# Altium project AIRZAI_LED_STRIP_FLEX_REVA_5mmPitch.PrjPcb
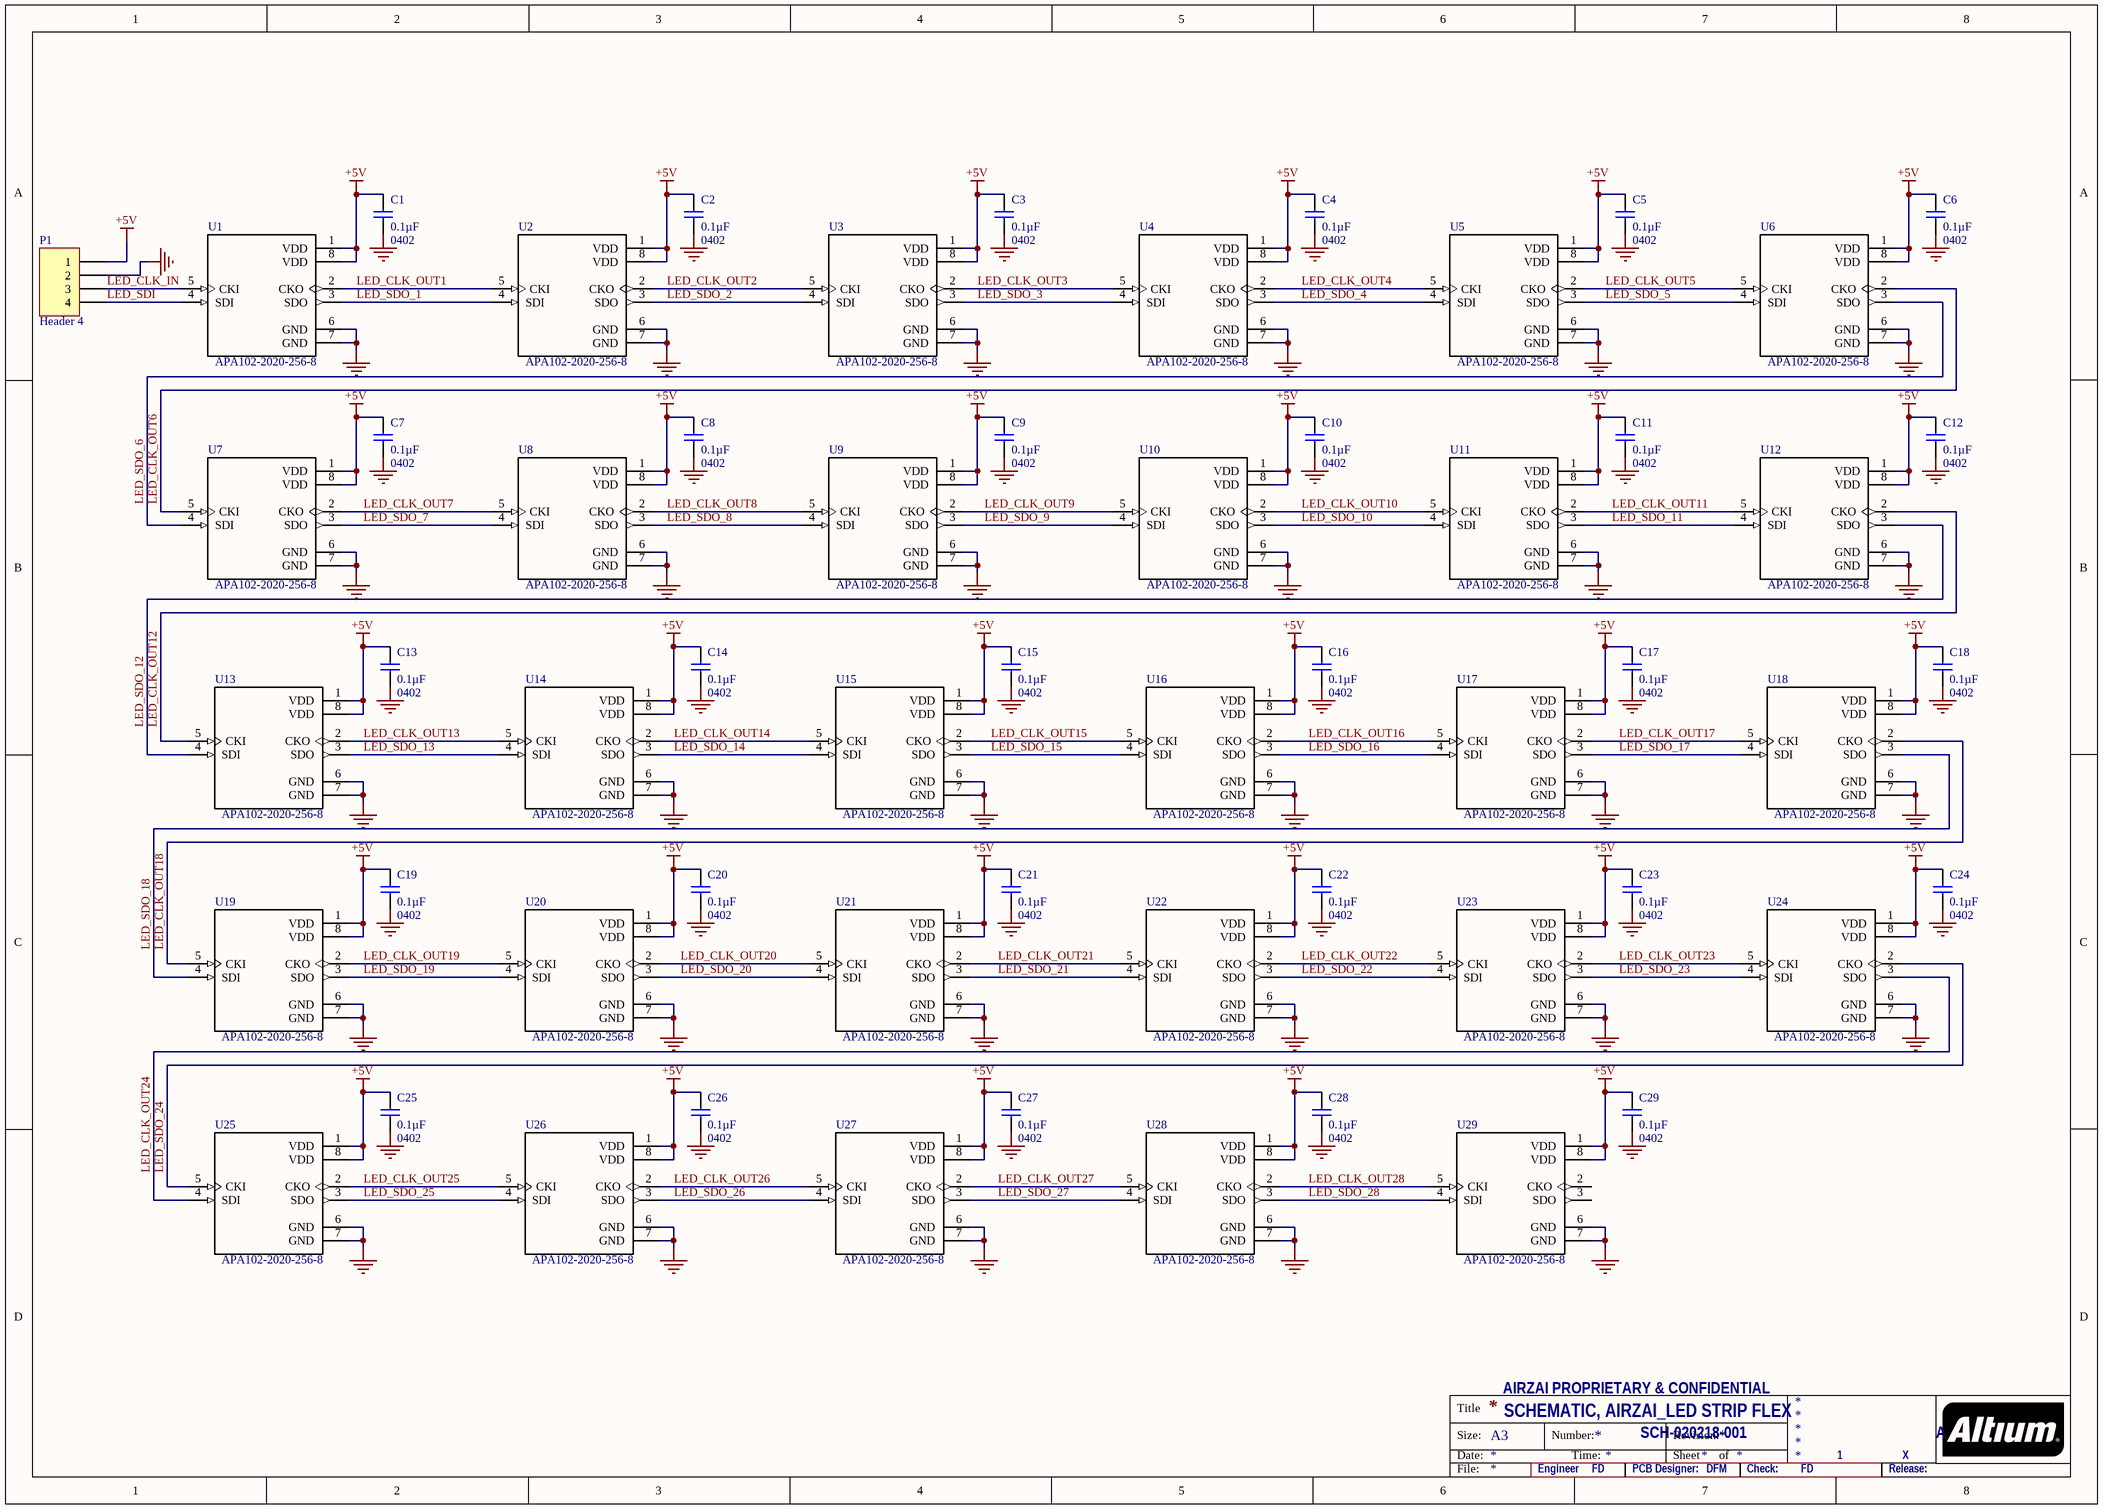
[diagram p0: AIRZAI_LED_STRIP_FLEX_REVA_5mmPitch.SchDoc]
1 sheet, 59 parts. Net scope: global (net labels, ports and power ports of the same name join across sheets).
Board file: AIRZAI_LED_STRIP_FLEX_REVA_5mmPitch.PcbDoc

## Sheet AIRZAI_LED_STRIP_FLEX_REVA_5mmPitch.SchDoc
size A3

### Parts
C1  0.1µF  Footprint: 0402  [0402CAP]
C2  0.1µF  Footprint: 0402  [0402CAP]
C3  0.1µF  Footprint: 0402  [0402CAP]
C4  0.1µF  Footprint: 0402  [0402CAP]
C5  0.1µF  Footprint: 0402  [0402CAP]
C6  0.1µF  Footprint: 0402  [0402CAP]
C7  0.1µF  Footprint: 0402  [0402CAP]
C8  0.1µF  Footprint: 0402  [0402CAP]
C9  0.1µF  Footprint: 0402  [0402CAP]
C10  0.1µF  Footprint: 0402  [0402CAP]
C11  0.1µF  Footprint: 0402  [0402CAP]
C12  0.1µF  Footprint: 0402  [0402CAP]
C13  0.1µF  Footprint: 0402  [0402CAP]
C14  0.1µF  Footprint: 0402  [0402CAP]
C15  0.1µF  Footprint: 0402  [0402CAP]
C16  0.1µF  Footprint: 0402  [0402CAP]
C17  0.1µF  Footprint: 0402  [0402CAP]
C18  0.1µF  Footprint: 0402  [0402CAP]
C19  0.1µF  Footprint: 0402  [0402CAP]
C20  0.1µF  Footprint: 0402  [0402CAP]
C21  0.1µF  Footprint: 0402  [0402CAP]
C22  0.1µF  Footprint: 0402  [0402CAP]
C23  0.1µF  Footprint: 0402  [0402CAP]
C24  0.1µF  Footprint: 0402  [0402CAP]
C25  0.1µF  Footprint: 0402  [0402CAP]
C26  0.1µF  Footprint: 0402  [0402CAP]
C27  0.1µF  Footprint: 0402  [0402CAP]
C28  0.1µF  Footprint: 0402  [0402CAP]
C29  0.1µF  Footprint: 0402  [0402CAP]
P1  Header 4  [FFC_4Pads]
U1  APA102-2020-256-8  [APA102–2020]
U2  APA102-2020-256-8  [APA102–2020]
U3  APA102-2020-256-8  [APA102–2020]
U4  APA102-2020-256-8  [APA102–2020]
U5  APA102-2020-256-8  [APA102–2020]
U6  APA102-2020-256-8  [APA102–2020]
U7  APA102-2020-256-8  [APA102–2020]
U8  APA102-2020-256-8  [APA102–2020]
U9  APA102-2020-256-8  [APA102–2020]
U10  APA102-2020-256-8  [APA102–2020]
U11  APA102-2020-256-8  [APA102–2020]
U12  APA102-2020-256-8  [APA102–2020]
U13  APA102-2020-256-8  [APA102–2020]
U14  APA102-2020-256-8  [APA102–2020]
U15  APA102-2020-256-8  [APA102–2020]
U16  APA102-2020-256-8  [APA102–2020]
U17  APA102-2020-256-8  [APA102–2020]
U18  APA102-2020-256-8  [APA102–2020]
U19  APA102-2020-256-8  [APA102–2020]
U20  APA102-2020-256-8  [APA102–2020]
U21  APA102-2020-256-8  [APA102–2020]
U22  APA102-2020-256-8  [APA102–2020]
U23  APA102-2020-256-8  [APA102–2020]
U24  APA102-2020-256-8  [APA102–2020]
U25  APA102-2020-256-8  [APA102–2020]
U26  APA102-2020-256-8  [APA102–2020]
U27  APA102-2020-256-8  [APA102–2020]
U28  APA102-2020-256-8  [APA102–2020]
U29  APA102-2020-256-8  [APA102–2020]

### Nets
+5V: C1.1 C2.1 C3.1 C4.1 C5.1 C6.1 C7.1 C8.1 C9.1 C10.1 C11.1 C12.1 C13.1 C14.1 C15.1 C16.1 C17.1 C18.1 C19.1 C20.1 C21.1 C22.1 C23.1 C24.1 C25.1 C26.1 C27.1 C28.1 C29.1 P1.1 U1.1(VDD) U1.8(VDD) U2.1(VDD) U2.8(VDD) U3.1(VDD) U3.8(VDD) U4.1(VDD) U4.8(VDD) U5.1(VDD) U5.8(VDD) U6.1(VDD) U6.8(VDD) U7.1(VDD) U7.8(VDD) U8.1(VDD) U8.8(VDD) U9.1(VDD) U9.8(VDD) U10.1(VDD) U10.8(VDD) U11.1(VDD) U11.8(VDD) U12.1(VDD) U12.8(VDD) U13.1(VDD) U13.8(VDD) U14.1(VDD) U14.8(VDD) U15.1(VDD) U15.8(VDD) U16.1(VDD) U16.8(VDD) U17.1(VDD) U17.8(VDD) U18.1(VDD) U18.8(VDD) U19.1(VDD) U19.8(VDD) U20.1(VDD) U20.8(VDD) U21.1(VDD) U21.8(VDD) U22.1(VDD) U22.8(VDD) U23.1(VDD) U23.8(VDD) U24.1(VDD) U24.8(VDD) U25.1(VDD) U25.8(VDD) U26.1(VDD) U26.8(VDD) U27.1(VDD) U27.8(VDD) U28.1(VDD) U28.8(VDD) U29.1(VDD) U29.8(VDD)
GND: C1.2 C2.2 C3.2 C4.2 C5.2 C6.2 C7.2 C8.2 C9.2 C10.2 C11.2 C12.2 C13.2 C14.2 C15.2 C16.2 C17.2 C18.2 C19.2 C20.2 C21.2 C22.2 C23.2 C24.2 C25.2 C26.2 C27.2 C28.2 C29.2 P1.2 U1.6(GND) U1.7(GND) U2.6(GND) U2.7(GND) U3.6(GND) U3.7(GND) U4.6(GND) U4.7(GND) U5.6(GND) U5.7(GND) U6.6(GND) U6.7(GND) U7.6(GND) U7.7(GND) U8.6(GND) U8.7(GND) U9.6(GND) U9.7(GND) U10.6(GND) U10.7(GND) U11.6(GND) U11.7(GND) U12.6(GND) U12.7(GND) U13.6(GND) U13.7(GND) U14.6(GND) U14.7(GND) U15.6(GND) U15.7(GND) U16.6(GND) U16.7(GND) U17.6(GND) U17.7(GND) U18.6(GND) U18.7(GND) U19.6(GND) U19.7(GND) U20.6(GND) U20.7(GND) U21.6(GND) U21.7(GND) U22.6(GND) U22.7(GND) U23.6(GND) U23.7(GND) U24.6(GND) U24.7(GND) U25.6(GND) U25.7(GND) U26.6(GND) U26.7(GND) U27.6(GND) U27.7(GND) U28.6(GND) U28.7(GND) U29.6(GND) U29.7(GND)
LED_CLK_IN: P1.3 U1.5(CKI)
LED_CLK_OUT1: U1.2(CKO) U2.5(CKI)
LED_CLK_OUT2: U2.2(CKO) U3.5(CKI)
LED_CLK_OUT3: U3.2(CKO) U4.5(CKI)
LED_CLK_OUT4: U4.2(CKO) U5.5(CKI)
LED_CLK_OUT5: U5.2(CKO) U6.5(CKI)
LED_CLK_OUT6: U6.2(CKO) U7.5(CKI)
LED_CLK_OUT7: U7.2(CKO) U8.5(CKI)
LED_CLK_OUT8: U8.2(CKO) U9.5(CKI)
LED_CLK_OUT9: U9.2(CKO) U10.5(CKI)
LED_CLK_OUT10: U10.2(CKO) U11.5(CKI)
LED_CLK_OUT11: U11.2(CKO) U12.5(CKI)
LED_CLK_OUT12: U12.2(CKO) U13.5(CKI)
LED_CLK_OUT13: U13.2(CKO) U14.5(CKI)
LED_CLK_OUT14: U14.2(CKO) U15.5(CKI)
LED_CLK_OUT15: U15.2(CKO) U16.5(CKI)
LED_CLK_OUT16: U16.2(CKO) U17.5(CKI)
LED_CLK_OUT17: U17.2(CKO) U18.5(CKI)
LED_CLK_OUT18: U18.2(CKO) U19.5(CKI)
LED_CLK_OUT19: U19.2(CKO) U20.5(CKI)
LED_CLK_OUT20: U20.2(CKO) U21.5(CKI)
LED_CLK_OUT21: U21.2(CKO) U22.5(CKI)
LED_CLK_OUT22: U22.2(CKO) U23.5(CKI)
LED_CLK_OUT23: U23.2(CKO) U24.5(CKI)
LED_CLK_OUT24: U24.3(SDO) U25.4(SDI)
LED_CLK_OUT25: U25.2(CKO) U26.5(CKI)
LED_CLK_OUT26: U26.2(CKO) U27.5(CKI)
LED_CLK_OUT27: U27.2(CKO) U28.5(CKI)
LED_CLK_OUT28: U28.2(CKO) U29.5(CKI)
LED_SDI: P1.4 U1.4(SDI)
LED_SDO_1: U1.3(SDO) U2.4(SDI)
LED_SDO_2: U2.3(SDO) U3.4(SDI)
LED_SDO_3: U3.3(SDO) U4.4(SDI)
LED_SDO_4: U4.3(SDO) U5.4(SDI)
LED_SDO_5: U5.3(SDO) U6.4(SDI)
LED_SDO_6: U6.3(SDO) U7.4(SDI)
LED_SDO_7: U7.3(SDO) U8.4(SDI)
LED_SDO_8: U8.3(SDO) U9.4(SDI)
LED_SDO_9: U9.3(SDO) U10.4(SDI)
LED_SDO_10: U10.3(SDO) U11.4(SDI)
LED_SDO_11: U11.3(SDO) U12.4(SDI)
LED_SDO_12: U12.3(SDO) U13.4(SDI)
LED_SDO_13: U13.3(SDO) U14.4(SDI)
LED_SDO_14: U14.3(SDO) U15.4(SDI)
LED_SDO_15: U15.3(SDO) U16.4(SDI)
LED_SDO_16: U16.3(SDO) U17.4(SDI)
LED_SDO_17: U17.3(SDO) U18.4(SDI)
LED_SDO_18: U18.3(SDO) U19.4(SDI)
LED_SDO_19: U19.3(SDO) U20.4(SDI)
LED_SDO_20: U20.3(SDO) U21.4(SDI)
LED_SDO_21: U21.3(SDO) U22.4(SDI)
LED_SDO_22: U22.3(SDO) U23.4(SDI)
LED_SDO_23: U23.3(SDO) U24.4(SDI)
LED_SDO_24: U24.2(CKO) U25.5(CKI)
LED_SDO_25: U25.3(SDO) U26.4(SDI)
LED_SDO_26: U26.3(SDO) U27.4(SDI)
LED_SDO_27: U27.3(SDO) U28.4(SDI)
LED_SDO_28: U28.3(SDO) U29.4(SDI)

Not connected (* = marked no-connect by the designer): U29 2(CKO) 3(SDO)

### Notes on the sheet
- AIRZAI PROPRIETARY & CONFIDENTIAL
- SCHEMATIC, AIRZAI_LED STRIP FLEX
- SCH-020218-001
- 1
- X
- A
- Engineer
- FD
- PCB Designer:
- DFM
- Check:
- Release:

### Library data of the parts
C1-C29 = C0402-100n: Capacitor, X7R, ±10%; Manufacturer: TDK; Manufacturer Part Number: C1005X7R1C104K; Note: 16V ±10% X7R; Case-Metric: 1005; Rated Voltage: 16 V; Tolerance: Â±20%
P1 = Header 4: Header, 4-Pin
U1-U29 = APA102-2020-256-8: DotStar Micro LEDs; MF: Adafruit Industries; MP: APA-102-2020-256-8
